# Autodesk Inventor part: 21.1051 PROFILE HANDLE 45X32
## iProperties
Created: 2007-02
Part Number: 21.1051 PROFILE HANDLE 45X32
Material: Aluminum-6061
Document SubType Name: Modeling
Designer: Andy Moles
Mass: 60.6682 g
Surface Area: 225.744 cm^2
Volume: 22.3868 cm^3
Density: 2.71 g/cm^3
Description: LENGTH = 1.89" BORE CENTERHOLE TO 8.2mm
Author: Andy Moles
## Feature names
1. Extrusion1
2. Extrusion2
